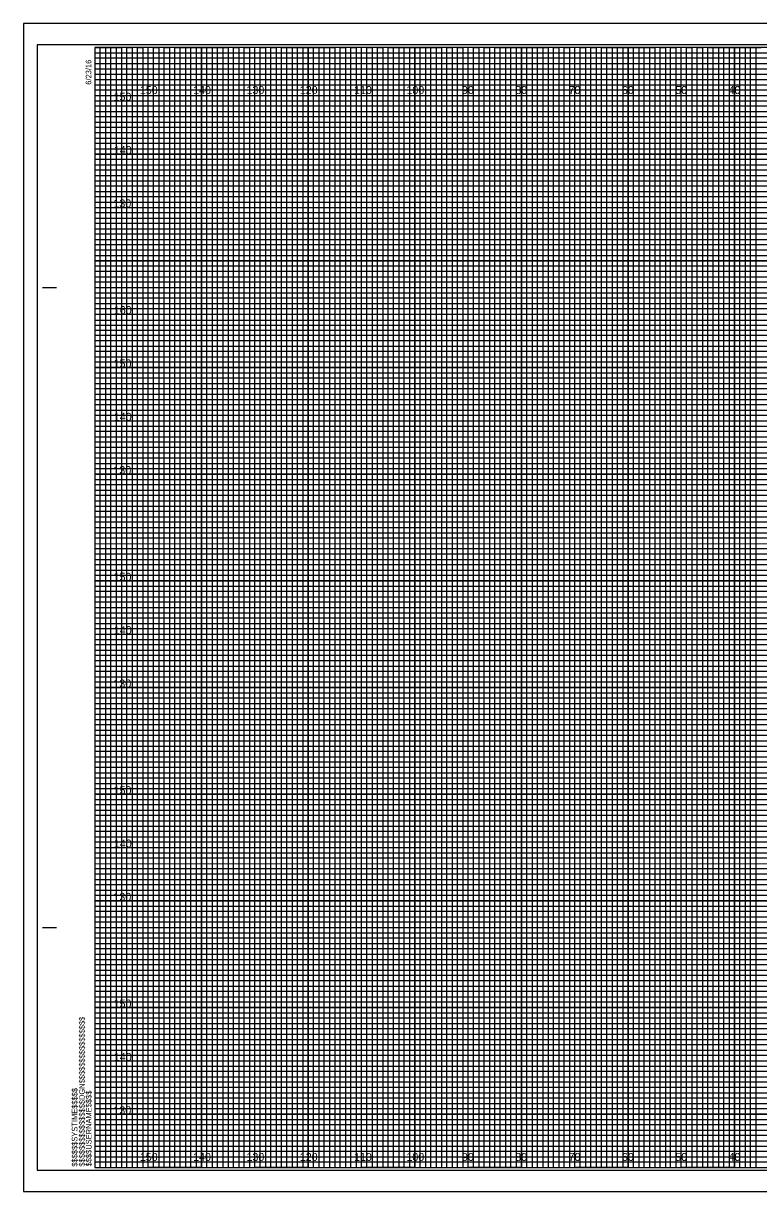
# Model space of a CAD drawing. Extents: x -13 to 323, y -5 to 3294.
# Drawn here: x -13.4 to 124.5, y -4.5 to 214.5 of the extents above; entities that cross this region are included whole.
import ezdxf

# ---------------------------------------------------------------- set-up
doc = ezdxf.new("R2010")
doc.units = 0
for name, color, linetype in [('Prop XS Elevation Labels', 7, 'Continuous'), ('Prop XS Offset Labels', 7, 'Continuous'), ('Sheet Cross Section CELL', 7, 'Continuous'), ('Sheet Cross Section Grid Major CELL', 7, 'Continuous'), ('Sheet Cross Section Grid Middle CELL', 7, 'Continuous'), ('Sheet Cross Section Grid Minor 1 CELL', 7, 'Continuous'), ('Sheet Cross Section Grid Minor 2 CELL', 7, 'Continuous'), ('Sheet Cutting Line CELL', 7, 'Continuous'), ('Sheet DOT Grid CELL', 7, 'Continuous'), ('Sheet Plot Border Inside CELL', 7, 'Continuous'), ('Sheet Plot Border Outside CELL', 7, 'Continuous')]:
    doc.layers.add(name, color=color, linetype=linetype)

msp = doc.modelspace()

# ---------------------------------------------------------------- linework, layer by layer
at = {"layer": 'Sheet Cross Section CELL'}
for p, q in [((-9.8, 165), (-7.3, 165)), ((-9.7, 165), (-7.2, 165)), ((-9.8, 45), (-7.3, 45)), ((-9.7, 45), (-7.2, 45)), ((0, 0), (0, 0)), ((0, 0), (0, 0)), ((0, 0), (0, 0)), ((0, 0), (0, 0)), ((0, 0), (0, 0)), ((0, 0), (0, 0)), ((0, 0), (0, 0))]:
    msp.add_line(p, q, dxfattribs=at)
msp.add_lwpolyline([(320, 210), (0, 210), (0, 0), (320, 0)], close=True, dxfattribs=at)
at = {"layer": 'Sheet Cross Section Grid Major CELL'}
for p, q in [((10, 210), (0, 210)), ((10, 0), (10, 210)), ((30, 210), (20, 210)), ((20, 210), (20, 0)), ((30, 0), (30, 210)), ((50, 210), (40, 210)), ((40, 210), (40, 0)), ((50, 0), (50, 210)), ((70, 210), (60, 210)), ((60, 210), (60, 0)), ((70, 0), (70, 210)), ((90, 210), (80, 210)), ((80, 210), (80, 0)), ((90, 0), (90, 210)), ((110, 210), (100, 210)), ((100, 210), (100, 0)), ((110, 0), (110, 210)), ((130, 210), (120, 210)), ((120, 210), (120, 0)), ((20, 0), (10, 0)), ((40, 0), (30, 0)), ((60, 0), (50, 0)), ((80, 0), (70, 0)), ((100, 0), (90, 0)), ((120, 0), (110, 0))]:
    msp.add_line(p, q, dxfattribs=at)
for points in [[(0, 200), (320, 200), (320, 190), (0, 190)], [(0, 180), (320, 180), (320, 170), (0, 170)], [(0, 160), (320, 160), (320, 150), (0, 150)], [(0, 140), (320, 140), (320, 130), (0, 130)], [(0, 120), (320, 120), (320, 110), (0, 110)], [(0, 100), (320, 100), (320, 90), (0, 90)], [(0, 80), (320, 80), (320, 70), (0, 70)], [(0, 60), (320, 60), (320, 50), (0, 50)], [(0, 40), (320, 40), (320, 30), (0, 30)], [(0, 20), (320, 20), (320, 10), (0, 10)]]:
    msp.add_lwpolyline(points, dxfattribs=at)
at = {"layer": 'Sheet Cross Section Grid Middle CELL'}
for points in [[(0, 210), (5, 210), (5, 0), (15, 0), (15, 210), (25, 210), (25, 0), (35, 0), (35, 210), (45, 210), (45, 0), (55, 0), (55, 210), (65, 210), (65, 0), (75, 0), (75, 210), (85, 210), (85, 0), (95, 0), (95, 210), (105, 210), (105, 0), (115, 0), (115, 210), (125, 210)], [(0, 205), (275, 205)], [(0, 185), (320, 185), (320, 195), (0, 195)], [(0, 165), (320, 165), (320, 175), (0, 175)], [(0, 145), (320, 145), (320, 155), (0, 155)], [(0, 125), (320, 125), (320, 135), (0, 135)], [(0, 105), (320, 105), (320, 115), (0, 115)], [(0, 85), (320, 85), (320, 95), (0, 95)], [(0, 65), (320, 65), (320, 75), (0, 75)], [(0, 45), (320, 45), (320, 55), (0, 55)], [(0, 25), (320, 25), (320, 35), (0, 35)], [(0, 5), (320, 5), (320, 15), (0, 15)]]:
    msp.add_lwpolyline(points, dxfattribs=at)
at = {"layer": 'Sheet Cross Section Grid Minor 1 CELL'}
for p, q in [((0, 209), (260, 209)), ((260, 207.98), (0, 207.98)), ((0, 207.98), (0, 207)), ((0, 207), (260, 207)), ((260, 205.89), (0, 205.89)), ((0, 205.89), (0, 204)), ((0, 204), (320, 204))]:
    msp.add_line(p, q, dxfattribs=at)
for points in [[(0, 203), (270, 203), (320, 203), (320, 202), (0, 202)], [(0, 201), (320, 201), (320, 199), (0, 199)], [(0, 198), (320, 198), (320, 197), (0, 196.98)], [(0, 196), (320, 196), (320, 194), (0, 194)], [(0, 193), (320, 193), (320, 192), (0, 192)], [(0, 191), (320, 191), (320, 189), (0, 189)], [(0, 188), (320, 188), (320, 187), (0, 187)], [(0, 186), (320, 186), (320, 184), (0, 184)], [(0, 183), (320, 183), (320, 182), (0, 182)], [(0, 181), (320, 181), (320, 179), (0, 179)], [(0, 178), (320, 178), (320, 177), (0, 177)], [(0, 176), (320, 176), (320, 173.95), (320, 173), (320, 172), (0, 172)], [(0, 174), (320, 174), (320, 173), (0, 173)], [(0, 171), (320, 171), (320, 169), (0, 169.03)], [(0, 169.03), (320, 169), (320, 168), (0, 168)], [(0, 167), (320, 167), (320, 166), (0, 166)], [(0, 164), (320, 164), (320, 163), (0, 163)], [(0, 162), (320, 162), (320, 161), (0, 161)], [(-0.07, 158.89), (320, 158.89), (320, 157.88), (-0.07, 157.88)], [(0, 157), (320, 157), (320, 156), (0, 156)], [(0, 154), (320, 154), (320, 153), (0, 153)], [(0, 152), (320, 152), (320, 151), (0, 151)], [(0, 149), (320, 149), (320, 148), (0, 148)], [(0, 147), (320, 147), (320, 146), (0, 146)], [(0, 144), (320, 144), (320, 143), (0, 143)], [(0, 142), (320, 142), (320, 141), (0, 141)], [(0, 139), (320, 139), (319.99, 137.98), (0, 138)], [(0, 137), (320, 137), (320, 136), (0, 136)], [(0, 134), (320, 134), (320, 133), (0, 133)], [(0, 132), (320, 132), (320, 131), (0, 131)], [(0, 129), (320, 129), (320, 128), (0, 128)], [(0, 127), (320, 127), (320, 126), (0, 126)], [(0, 124), (320, 124), (320, 123), (0, 123)], [(0, 122), (320, 122), (320, 121), (0, 121)], [(0, 119), (320, 119), (320, 118), (0, 118)], [(0, 116.99), (320.07, 116.91), (320, 116), (0, 116)], [(0, 114), (320, 114), (320, 113), (0, 113)], [(0, 112), (320, 112), (320, 111), (0, 111)], [(0, 109), (320, 109), (320, 108), (0, 108)], [(0, 107), (320, 107), (320, 106), (0, 106)], [(0, 104), (320, 104), (320, 103), (0, 103)], [(0, 102), (320, 102), (320, 101), (0, 101)], [(0, 99), (320, 99), (320, 98), (0, 98)], [(0, 97), (320, 97), (320, 96), (0, 96)], [(0, 94), (320, 94), (320, 93), (0, 93)], [(0, 92), (320, 92), (320, 91), (0, 91)], [(0, 89), (320, 89), (320, 88), (0, 88)], [(0, 87), (320, 87), (320, 86), (0, 86)], [(0, 84), (320, 84), (320, 83), (0, 83)], [(0, 82), (320, 82), (320, 81), (0, 81)], [(0, 79), (320, 79), (319.99, 77.98), (0, 78)], [(0, 77), (320, 77), (320, 76), (0, 76)], [(0, 74), (320, 74), (320, 73), (0, 73)], [(0, 72), (320, 72), (320, 71), (0, 71)], [(0, 69), (320, 69), (320, 68), (0, 68)], [(0, 67), (320, 67), (320, 66), (0, 66)], [(0, 64), (320, 64), (320, 63), (0, 63)], [(0, 62), (320, 62), (320, 61), (0, 61)], [(0, 59), (320, 59), (320, 58), (0, 58)], [(0, 56.99), (320.07, 56.91), (320, 56), (0, 56)], [(0, 54), (320, 54), (320, 53), (0, 53)], [(0, 52), (320, 52), (320, 51), (0, 51)], [(0, 49), (320, 49), (320, 48), (0, 48)], [(0, 47), (320, 47), (320, 46), (0, 46)], [(0, 44), (320, 44), (320, 43), (0, 43)], [(0, 42), (320, 42), (320, 41), (0, 41)], [(0, 39), (320, 39), (320, 38), (0, 38)], [(0, 37), (320, 37), (320, 36), (0, 36)], [(0, 34), (320, 34), (320, 33), (0, 33)], [(0, 32), (320, 32), (320, 31), (0, 31)], [(0, 29), (320, 29), (320, 28), (0, 28)], [(0, 27), (320, 27), (320, 26), (0, 26)], [(0, 24), (320, 24), (320, 23), (0, 23)], [(0, 22), (320, 22), (320, 21), (0, 21)], [(0, 19), (320, 19), (320, 18), (0, 18)], [(0, 17), (320, 17), (320, 16), (0, 16)], [(0, 14), (320, 14), (320, 13), (0, 13)], [(0, 12), (320, 12), (320, 11), (0, 11)], [(0, 9), (320, 9), (320, 8), (0, 8)], [(0, 7), (320, 7), (320, 6), (0, 6)], [(0, 4), (320, 4), (320, 3), (0, 3)], [(0, 2), (320, 2), (320, 1), (0, 1)]]:
    msp.add_lwpolyline(points, dxfattribs=at)
at = {"layer": 'Sheet Cross Section Grid Minor 2 CELL'}
for points in [[(0, 0), (1, 0), (1, 210), (2, 210), (2, 0)], [(2, 0), (3, 0), (3, 210), (4, 210), (4, 0)], [(5, 0), (6, 0), (6, 210), (7, 210), (7, 0)], [(7, 0), (8, 0), (8, 210), (9, 210), (9, 0)], [(10, 0), (11, 0), (11, 210), (12, 210), (12, 0)], [(12, 0), (13, 0), (13, 210), (14, 210), (14, 0)], [(15, 0), (16, 0), (16, 210), (17, 210), (17, 0)], [(17, 0), (18, 0), (18, 210), (19, 210), (19, 0)], [(20, 0), (21, 0), (21, 210), (22, 210), (22, 0)], [(22, 0), (23, 0), (23, 210), (24, 210), (24, 0)], [(25, 0), (26, 0), (26, 210), (27, 210), (27, 0)], [(27, 0), (28, 0), (28, 210), (29, 210), (29, 0)], [(30, 0), (31, 0), (31, 210), (32, 210), (32, 0)], [(32, 0), (33, 0), (33, 210), (34, 210), (34, 0)], [(35, 0), (36, 0), (36, 210), (37, 210), (37, 0)], [(37, 0), (38, 0), (38, 210), (39, 210), (39, 0)], [(40, 0), (41, 0), (41, 210), (42, 210), (42, 0)], [(42, 0), (43, 0), (43, 210), (44, 210), (44, 0)], [(45, 0), (46, 0), (46, 210), (47, 210), (47, 0)], [(47, 0), (48, 0), (48, 210), (49, 210), (49, 0)], [(50, 0), (51, 0), (51, 210), (52, 210), (52, 0)], [(52, 0), (53, 0), (53, 210), (54, 210), (54, 0)], [(55, 0), (56, 0), (56, 210), (57, 210), (57, 0)], [(57, 0), (58, 0), (58, 210), (59, 210), (59, 0)], [(60, 0), (61, 0), (61, 210), (62, 210), (62, 0)], [(62, 0), (63, 0), (63, 210), (64, 210), (64, 0)], [(65, 0), (66, 0), (66, 210), (67, 210), (67, 0)], [(67, 0), (68, 0), (68, 210), (69, 210), (69, 0)], [(70, 0), (71, 0), (71, 210), (72, 210), (72, 0)], [(72, 0), (73, 0), (73, 210), (74, 210), (74, 0)], [(75, 0), (76, 0), (76, 210), (77, 210), (77, 0)], [(77, 0), (78, 0), (78, 210), (79, 210), (79, 0)], [(80, 0), (81, 0), (81, 210), (82, 210), (82, 0)], [(82, 0), (83, 0), (83, 210), (84, 210), (84, 0)], [(85, 0), (86, 0), (86, 210), (87, 210), (87, 0)], [(87, 0), (88, 0), (88, 210), (89, 210), (89, 0)], [(90, 0), (91, 0), (91, 210), (92, 210), (92, 0)], [(92, 0), (93, 0), (93, 210), (94, 210), (94, 0)], [(95, 0), (96, 0), (96, 210), (97, 210), (97, 0)], [(97, 0), (98, 0), (98, 210), (99, 210), (99, 0)], [(100, 0), (101, 0), (101, 210), (102, 210), (102, 0)], [(102, 0), (103, 0), (103, 210), (104, 210), (104, 0)], [(105, 0), (106, 0), (106, 210), (107, 210), (107, 0)], [(107, 0), (108, 0), (108, 210), (109, 210), (109, 0)], [(110, 0), (111, 0), (111, 210), (112, 210), (112, 0)], [(112, 0), (113, 0), (113, 210), (114, 210), (114, 0)], [(115, 0), (116, 0), (116, 210), (117, 210), (117, 0)], [(117, 0), (118, 0), (118, 210), (119, 210), (119, 0)], [(120, 0), (121, 0), (121, 210), (122, 210), (122, 0)], [(122, 0), (123, 0), (123, 210), (124, 210), (124, 0)]]:
    msp.add_lwpolyline(points, dxfattribs=at)
at = {"layer": 'Sheet Cutting Line CELL'}
for p, q in [((323.3, 214.5), (-13.4, 214.5)), ((-13.4, 214.5), (-13.4, -4.5)), ((-13.4, -4.5), (323.3, -4.5))]:
    msp.add_line(p, q, dxfattribs=at)
at = {"layer": 'Sheet DOT Grid CELL'}
for p, q in [((10, 0), (10, 210)), ((20, 0), (20, 210)), ((30, 0), (30, 210)), ((40, 0), (40, 210)), ((50, 0), (50, 210)), ((60, 0), (60, 210)), ((70, 0), (70, 210)), ((80, 0), (80, 210)), ((90, 0), (90, 210)), ((100, 0), (100, 210)), ((110, 0), (110, 210)), ((120, 0), (120, 210)), ((0, 200), (320, 200)), ((0, 190), (320, 190)), ((0, 180), (320, 180)), ((0, 170), (320, 170)), ((0, 160), (320, 160)), ((0, 150), (320, 150)), ((0, 140), (320, 140)), ((0, 130), (320, 130)), ((0, 120), (320, 120)), ((0, 110), (320, 110)), ((0, 100), (320, 100)), ((0, 90), (320, 90)), ((0, 80), (320, 80)), ((0, 70), (320, 70)), ((0, 60), (320, 60)), ((0, 50), (320, 50)), ((0, 40), (320, 40)), ((0, 30), (320, 30)), ((0, 20), (320, 20)), ((0, 10), (320, 10))]:
    msp.add_line(p, q, dxfattribs=at)
at = {"layer": 'Sheet Plot Border Inside CELL'}
msp.add_lwpolyline([(-10.8, -0.5), (322.4, -0.5), (322.4, 210.5), (-10.8, 210.5)], close=True, dxfattribs=at)
at = {"layer": 'Sheet Plot Border Outside CELL'}
msp.add_lwpolyline([(-13.4, -4.5), (323.3, -4.5), (323.3, 214.5), (-13.4, 214.5)], close=True, dxfattribs=at)

# ---------------------------------------------------------------- texts
at = {"layer": 'Prop XS Elevation Labels'}
for s, p in [('150', (3.52, 200)), ('140', (3.57, 190)), ('130', (3.49, 180)), ('160', (3.57, 160)), ('150', (3.52, 150)), ('140', (3.57, 140)), ('130', (3.49, 130)), ('150', (3.52, 110)), ('140', (3.57, 100)), ('130', (3.49, 90)), ('150', (3.52, 70)), ('140', (3.57, 60)), ('130', (3.49, 50)), ('150', (3.52, 30)), ('140', (3.57, 20)), ('130', (3.49, 10))]:
    msp.add_text(s, height=1.5, dxfattribs=at).set_placement(p)
at = {"layer": 'Prop XS Offset Labels'}
for s, p in [('150', (8.44, 201.25)), ('140', (18.44, 201.25)), ('130', (28.44, 201.25)), ('120', (38.44, 201.25)), ('110', (48.62, 201.25)), ('100', (58.44, 201.25)), ('90', (68.86, 201.25)), ('80', (78.86, 201.25)), ('70', (88.86, 201.25)), ('60', (98.86, 201.25)), ('50', (108.86, 201.25)), ('40', (118.86, 201.25)), ('150', (8.44, 1.25)), ('140', (18.44, 1.25)), ('130', (28.44, 1.25)), ('120', (38.44, 1.25)), ('110', (48.62, 1.25)), ('100', (58.44, 1.25)), ('90', (68.86, 1.25)), ('80', (78.86, 1.25)), ('70', (88.86, 1.25)), ('60', (98.86, 1.25)), ('50', (108.86, 1.25)), ('40', (118.86, 1.25))]:
    msp.add_text(s, height=1.5, dxfattribs=at).set_placement(p)
at = {"layer": 'Sheet Cross Section CELL'}
for s, p in [('6/23/16', (-0.65, 203)), ('$$$$$$$$$$$$$$$$DGN$$$$$$$$$$$$$$$$', (-1.88, 0.18)), ('$$$$$$SYSTIME$$$$$', (-3.26, 0.18)), ('$$$$USERNAME$$$$', (-0.62, 0.23))]:
    msp.add_text(s, height=1.05, rotation=90, dxfattribs=at).set_placement(p)

doc.saveas('drawing.dxf')
